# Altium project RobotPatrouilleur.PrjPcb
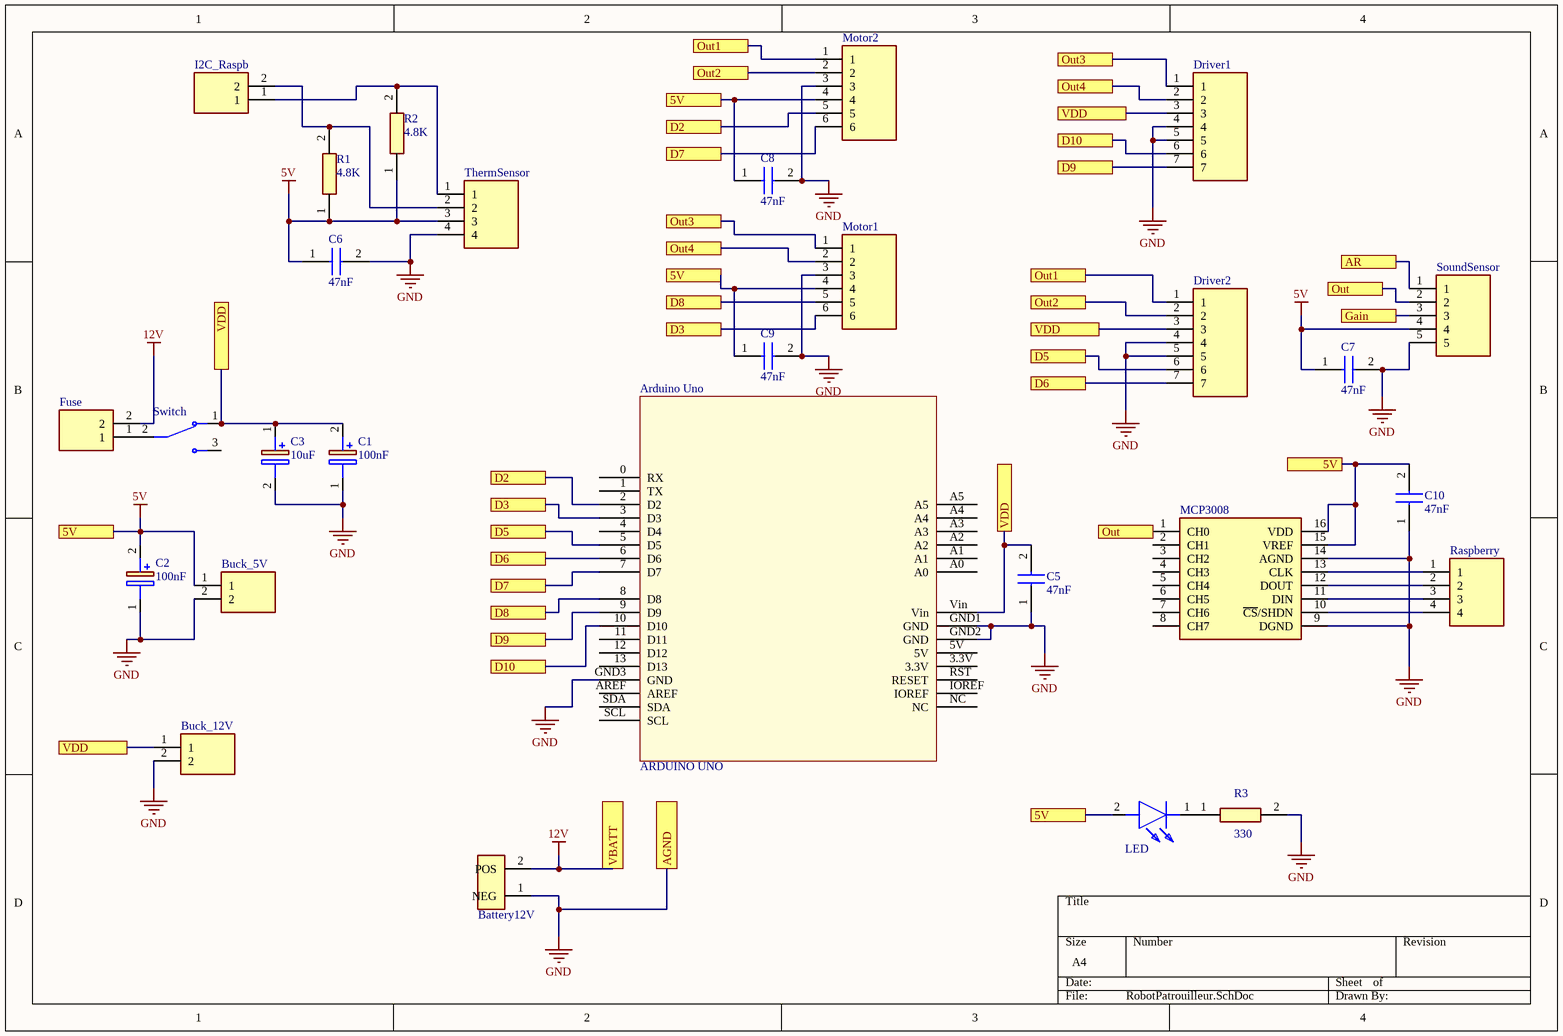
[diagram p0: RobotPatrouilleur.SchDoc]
1 sheet, 28 parts. Net scope: flat (ports and power ports of the same name join across sheets).
Board file: PCB1.PcbDoc

## Sheet RobotPatrouilleur.SchDoc
size A4

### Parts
Arduino_Uno  ARDUINO UNO  [Arduino Uno]
Battery12V  XT60-M  [AMASS_XT60-M]  (value not drawn)
Buck_5V  B02B-XASK-1_LF__SN_  [SHDR2W60P0X250_1X2_750X640X880P]  (value not drawn)
Buck_12V  B02B-XASK-1_LF__SN_  [SHDR2W60P0X250_1X2_750X640X880P]  (value not drawn)
C1  100nF  [TAP106M016DCS]
C2  100nF  [TAP106M016DCS]
C3  10uF  [CAPPRD200W52D500H1250]
C5  47nF  [CAPC2012X94N]
C6  47nF  [CAPC2012X94N]
C7  47nF  [CAPC2012X94N]
C8  47nF  [CAPC2012X94N]
C9  47nF  [CAPC2012X94N]
C10  47nF  [CAPC2012X94N]
Driver1  B7B-PH-K-S_LF__SN_  [SHDR7W50P0X200_1X7_1590X450X600P]  (value not drawn)
Driver2  B7B-PH-K-S_LF__SN_  [SHDR7W50P0X200_1X7_1590X450X600P]  (value not drawn)
Fuse  0031.8201  [0031.8201]  (value not drawn)
I2C_Raspb  B02B-XASK-1_LF__SN_  [SHDR2W60P0X250_1X2_750X640X880P]  (value not drawn)
LED  HSMG-C191  [LEDC1608X70N]  (value not drawn)
MCP3008  MCP3008-I_P  [DIP781W56P254L1918H533Q16N]  (value not drawn)
Motor1  B6B-EH-A_LF__SN_  [B6BEHALFSN]  (value not drawn)
Motor2  B6B-EH-A_LF__SN_  [B6BEHALFSN]  (value not drawn)
R1  4.8K  [RESC2012X65N]
R2  4.8K  [RESC2012X65N]
R3  330  [RESC2012X50N]
Raspberry  B4B-XH-A_LF__SN_  [B4BXHALFSN]  (value not drawn)
SoundSensor  22-23-2051  [HDRV5W64P0X254_1X5_1255X635X818P]  (value not drawn)
Switch  100SP1T1B4M2QE  [SW_100SP1T1B4M2QE]  (value not drawn)
ThermSensor  B4B-XH-A_LF__SN_  [B4BXHALFSN]  (value not drawn)

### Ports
5V, AGND, AR, D2, D3, D5, D6, D7, D8, D9, D10, Gain, Out, Out1, Out2, Out3, Out4, VBATT, VDD

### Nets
5V: Buck_5V.1 C2.2(+) C6.1 C7.1 C8.1 C9.1 C10.2 LED.2(A) MCP3008.15(VREF) MCP3008.16(VDD) Motor1.4 Motor2.4 R1.1 R2.1 SoundSensor.4 ThermSensor.3 ; port 5V
12V: Battery12V.2(POS) Fuse.2 ; port VBATT
GND: Arduino_Uno.GND1(GND) Arduino_Uno.GND2(GND) Arduino_Uno.GND3(GND) Battery12V.1(NEG) Buck_5V.2 Buck_12V.2 C1.1(-) C2.1(-) C3.2(-) C5.1 C6.2 C7.2 C8.2 C9.2 C10.1 Driver1.4 Driver1.5 Driver2.4 Driver2.5 MCP3008.9(DGND) MCP3008.14(AGND) Motor1.3 Motor2.3 R3.2 SoundSensor.5 ThermSensor.4 ; port AGND
NetArduino_Uno_2: Arduino_Uno.2(D2) Motor2.5 ; port D2
NetArduino_Uno_3: Arduino_Uno.3(D3) Motor1.6 ; port D3
NetArduino_Uno_5: Arduino_Uno.5(D5) Driver2.6 ; port D5
NetArduino_Uno_6: Arduino_Uno.6(D6) Driver2.7 ; port D6
NetArduino_Uno_7: Arduino_Uno.7(D7) Motor2.6 ; port D7
NetArduino_Uno_8: Arduino_Uno.8(D8) Motor1.5 ; port D8
NetArduino_Uno_9: Arduino_Uno.9(D9) Driver1.7 ; port D9
NetArduino_Uno_10: Arduino_Uno.10(D10) Driver1.6 ; port D10
NetArduino_Uno_Vin: Arduino_Uno.Vin Buck_12V.1 C1.2(+) C3.1(+) C5.2 Driver1.3 Driver2.3 Switch.1 ; port VDD
NetDriver1_1: Driver1.1 Motor1.1 ; port Out3
NetDriver1_2: Driver1.2 Motor1.2 ; port Out4
NetDriver2_1: Driver2.1 Motor2.1 ; port Out1
NetDriver2_2: Driver2.2 Motor2.2 ; port Out2
NetFuse_1: Fuse.1 Switch.2
NetI2C_Raspb_1: I2C_Raspb.1 R2.2 ThermSensor.1
NetI2C_Raspb_2: I2C_Raspb.2 R1.2 ThermSensor.2
NetLED_1: LED.1(K) R3.1
NetMCP3008_1: MCP3008.1(CH0) SoundSensor.2 ; port Out
NetMCP3008_10: MCP3008.10(~{CS}/SHDN) Raspberry.4
NetMCP3008_11: MCP3008.11(DIN) Raspberry.3
NetMCP3008_12: MCP3008.12(DOUT) Raspberry.2
NetMCP3008_13: MCP3008.13(CLK) Raspberry.1
NetSoundSensor_1: SoundSensor.1 ; port AR
NetSoundSensor_3: SoundSensor.3 ; port Gain

Not connected (* = marked no-connect by the designer): Arduino_Uno 0(RX) 1(TX) 3.3V 4(D4) 5V 11(D11) 12(D12) 13(D13) A0 A1 A2 A3 A4 A5 AREF IOREF NC RST(RESET) SCL SDA; MCP3008 2(CH1) 3(CH2) 4(CH3) 5(CH4) 6(CH5) 7(CH6) 8(CH7); Switch 3

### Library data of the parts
Battery12V = XT60-M: Plug; DC supply; XT60; male; PIN: 2; for cable; soldered; 30A; 500V; MF: AMASS
Buck_5V Buck_12V I2C_Raspb = B02B-XASK-1_LF__SN_: Connector; Manufacturer_Name: JST (JAPAN SOLDERLESS TERMINALS); Manufacturer_Part_Number: B02B-XASK-1(LF)(SN)
C1 = TAP104K050SCS: Capacitor Polarised TAP104K050SCS; Manufacturer_Name: AVX
C2 = TAP104K050SCS: Capacitor Polarised; Manufacturer_Name: AVX
C3 = 860240672002: Capacitor Polarised; Manufacturer_Name: Wurth Elektronik
C5-C10 = 08055C473JAT2A: Capacitor; Manufacturer_Name: AVX
Driver1 Driver2 = B7B-PH-K-S_LF__SN_: Connector; Manufacturer_Name: JST (JAPAN SOLDERLESS TERMINALS); Manufacturer_Part_Number: B7B-PH-K-S(LF)(SN)
Fuse = 0031.8201: Connector; Manufacturer_Name: SCHURTER
LED = HSMG-C191: LED; Manufacturer_Name: Avago Technologies
MCP3008 = MCP3008-I_P: Integrated Circuit; Manufacturer_Name: Microchip; Manufacturer_Part_Number: MCP3008-I/P
Motor1 Motor2 = B6B-EH-A_LF__SN_: Connector; Manufacturer_Name: JST (JAPAN SOLDERLESS TERMINALS); Manufacturer_Part_Number: B6B-EH-A(LF)(SN)
R1 = CRG0805F470R: Resistor CRG0805F470R; Manufacturer_Name: TE Connectivity
R2 = CRG0805F470R: Manufacturer_Name: TE Connectivity
R3 = CRCW0805330RFKEA: Resistor 330; Manufacturer_Name: Vishay
Raspberry ThermSensor = B4B-XH-A_LF__SN_: Connector; Manufacturer_Name: JST Sales America; Manufacturer_Part_Number: B4B-XH-A(LF)(SN)
SoundSensor = 22-23-2051: Connector; Manufacturer_Name: Molex
Switch = 100SP1T1B4M2QE: Toggle Switch SPDT Through Hole; MF: E-Switch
